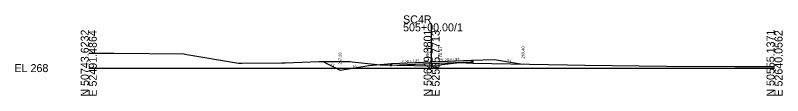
# Model space of a CAD drawing. Extents: x 9740 to 17409, y 8856 to 28416.
# Drawn here: x 9740.2 to 10008.7, y 25861.7 to 25889.9 of the extents above; entities that cross this region are included whole.
import ezdxf

# ---------------------------------------------------------------- set-up
doc = ezdxf.new("R2010")
doc.units = 0
for name, color, linetype in [('Level 10', 7, 'Continuous'), ('Level 11', 7, 'Continuous'), ('Level 12', 7, 'Continuous'), ('Level 32', 7, 'Continuous'), ('Level 33', 7, 'Continuous'), ('Level 59', 7, 'Continuous'), ('Level 6', 7, 'Continuous'), ('Level 60', 7, 'Continuous'), ('Level 63', 7, 'Continuous'), ('Level 7', 7, 'Continuous')]:
    doc.layers.add(name, color=color, linetype=linetype)

msp = doc.modelspace()

# ---------------------------------------------------------------- linework, layer by layer
at = {"layer": 'Level 11'}
for p, q in [((9899.85, 25873.82), (9899.85, 25874.12)), ((9900.35, 25873.84), (9899.85, 25873.82)), ((9899.85, 25873.48), (9900.35, 25873.5)), ((9900.35, 25873.5), (9900.35, 25873.84)), ((9871.85, 25872.67), (9871.35, 25872.65)), ((9871.35, 25872.65), (9871.35, 25872.31)), ((9871.35, 25872.31), (9871.85, 25872.33)), ((9871.85, 25872.97), (9871.85, 25872.67))]:
    msp.add_line(p, q, dxfattribs=at)
at = {"layer": 'Level 12'}
for p, q in [((9899.85, 25873.48), (9885.85, 25872.91)), ((9885.85, 25872.91), (9871.85, 25872.33))]:
    msp.add_line(p, q, dxfattribs=at)
at = {"layer": 'Level 59'}
for p, q in [((9871.85, 25872.97), (9885.85, 25873.55)), ((9885.85, 25873.55), (9899.85, 25874.12))]:
    msp.add_line(p, q, dxfattribs=at)
at = {"layer": 'Level 6'}
for p, q in [((9899.85, 25874.12), (9907.85, 25874.45)), ((9863.85, 25872.31), (9871.85, 25872.97))]:
    msp.add_line(p, q, dxfattribs=at)
at = {"layer": 'Level 60'}
for p, q in [((9765.85, 25876.61), (9773.79, 25876.61)), ((9773.79, 25876.61), (9774.58, 25876.62)), ((9774.58, 25876.62), (9799.18, 25876.44)), ((9799.18, 25876.44), (9799.49, 25876.33)), ((9799.49, 25876.33), (9818.27, 25873.12)), ((9818.27, 25873.12), (9818.8, 25873.08)), ((9818.8, 25873.08), (9819.4, 25873.09)), ((9819.4, 25873.09), (9833.44, 25873.22)), ((9833.44, 25873.22), (9834.56, 25873.26)), ((9834.56, 25873.26), (9846.51, 25873.69)), ((9846.51, 25873.69), (9856.2, 25873.66)), ((9856.2, 25873.66), (9857.3, 25873.66)), ((9857.3, 25873.66), (9858.06, 25873.57)), ((9858.06, 25873.57), (9866.79, 25872.61)), ((9889.42, 25872.59), (9895.55, 25873.31)), ((9895.55, 25873.31), (9900.31, 25873.08)), ((9900.31, 25873.08), (9933.34, 25872.57)), ((9866.79, 25872.61), (9867.71, 25872.49)), ((9867.71, 25872.49), (9885.85, 25872.23)), ((9885.85, 25872.23), (9887.78, 25872.2)), ((9887.78, 25872.2), (9889.42, 25872.59)), ((9933.34, 25872.57), (9939.48, 25872.41)), ((9939.48, 25872.41), (9968.06, 25872.09)), ((9968.06, 25872.09), (9992.04, 25871.93)), ((9992.04, 25871.93), (10005.85, 25871.93))]:
    msp.add_line(p, q, dxfattribs=at)
at = {"layer": 'Level 63'}
for p, q in [((9885.85, 25871.38), (9885.85, 25887.09)), ((9765.85, 25871.38), (9885.85, 25871.38)), ((9885.85, 25871.38), (10005.85, 25871.38))]:
    msp.add_line(p, q, dxfattribs=at)
at = {"layer": 'Level 7'}
for p, q in [((9847.76, 25873.69), (9853.85, 25870.64)), ((9907.85, 25874.45), (9917.67, 25872.81)), ((9853.85, 25870.64), (9863.85, 25872.31))]:
    msp.add_line(p, q, dxfattribs=at)

# ---------------------------------------------------------------- texts
at = {"layer": 'Level 10'}
msp.add_text('268.85', height=1, rotation=90, dxfattribs=at).set_placement((9884.85, 25875.19))
at = {"layer": 'Level 32'}
for s, rotation, p in [('2:1', 333.435, (9850.41, 25872.64)), ('0.041 FT./FT.', 2.3478, (9875.59, 25873.38)), ('0.041 FT./FT.', 2.3478, (9889.59, 25873.95)), ('6:1', 350.5377, (9912.37, 25873.95)), ('6:1', 9.4623, (9858.29, 25871.63))]:
    msp.add_text(s, height=0.75, rotation=rotation, dxfattribs=at).set_placement(p)
at = {"layer": 'Level 33'}
for s, p in [('269.40', (9918.35, 25874.78)), ('267.26', (9854.35, 25872.64))]:
    msp.add_text(s, height=1, rotation=90, dxfattribs=at).set_placement(p)
at = {"layer": 'Level 59'}
msp.add_text(' 270.17', height=1.2, rotation=90, dxfattribs=at).set_placement((9889.44, 25873.55))
at = {"layer": 'Level 63'}
for s, p in [('SC4R', (9875.85, 25887.09)), ('505+00.00/1', (9875.85, 25884.29)), ('EL 268', (9739.85, 25869.98))]:
    msp.add_text(s, height=2.8, dxfattribs=at).set_placement(p)
for s, p in [('N 50743.6232', (9765.85, 25861.38)), ('E 52491.4864', (9768.65, 25861.38)), ('N 50649.3801', (9885.85, 25861.38)), ('E 52565.7713', (9888.65, 25861.38)), ('N 50555.1371', (10005.85, 25861.38)), ('E 52640.0562', (10008.65, 25861.38))]:
    msp.add_text(s, height=2.8, rotation=90, dxfattribs=at).set_placement(p)

doc.saveas('drawing.dxf')
